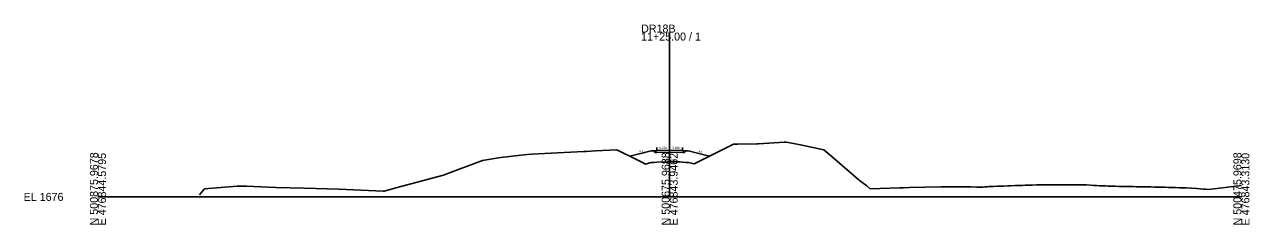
# Model space of a CAD drawing. Extents: x -26 to 403, y -10 to 2578.
# Drawn here: x -25.7 to 402.8, y 990.3 to 1060.4 of the extents above; entities that cross this region are included whole.
import ezdxf

# ---------------------------------------------------------------- set-up
doc = ezdxf.new("R2010")
doc.units = 0
for name, color, linetype in [('Exist Cross Section Cell', 7, 'Continuous'), ('Exist XS Center Line Elevation Label', 7, 'Continuous'), ('Exist XS Ground Line', 7, 'Continuous'), ('Prop XS Ditch Slope Text', 7, 'Continuous'), ('Prop XS Earthwork Shape', 7, 'Continuous'), ('Prop XS EOT Tick Mark', 7, 'Continuous'), ('Prop XS Finish Grade', 7, 'Continuous'), ('Prop XS Finish Grade Earthwork', 7, 'Continuous'), ('Prop XS Finish Grade Pavement', 7, 'Continuous'), ('Prop XS Hydro Typical Ditch Data', 7, 'Continuous'), ('Prop XS Pvmt Edge Slope', 7, 'Continuous'), ('Prop XS SE Text', 7, 'Continuous'), ('Prop XS Shoulder Borrow Shape', 7, 'Continuous'), ('Prop XS Subgrade Earthwork', 7, 'Continuous')]:
    doc.layers.add(name, color=color, linetype=linetype)

msp = doc.modelspace()

# ---------------------------------------------------------------- linework, layer by layer
at = {"layer": 'Exist Cross Section Cell'}
for p, q in [((200, 1000), (200, 1057.57)), ((0, 1000), (200, 1000)), ((200, 1000), (400, 1000))]:
    msp.add_line(p, q, dxfattribs=at)
at = {"layer": 'Exist XS Ground Line'}
msp.add_lwpolyline([(35.58, 1000.75), (37.28, 1002.81), (48.69, 1003.73), (52.02, 1003.71), (62.23, 1003.32), (72.12, 1003.1), (80.24, 1002.83), (84.26, 1002.72), (99.79, 1001.95), (100.15, 1002.02), (104.65, 1003.26), (120.85, 1007.62), (122.04, 1008.03), (134.49, 1012.78), (140.78, 1013.78), (150.17, 1014.86), (151.66, 1015.01), (160.86, 1015.41), (169.99, 1015.91), (170.86, 1015.94), (174.1, 1016.14), (181.48, 1016.52), (188.86, 1012.86), (190.02, 1012.28), (191.56, 1011.51), (193.11, 1011.9), (193.56, 1012.01), (194.3, 1012.08), (195.56, 1012.18), (199.05, 1012.26), (200.06, 1012.28), (203.54, 1012.22), (204.56, 1012.2), (205.82, 1012.1), (206.56, 1012.04), (208.1, 1011.66), (208.56, 1011.55), (210.7, 1012.61), (222.38, 1018.49), (223.38, 1018.49), (223.84, 1018.5), (230.53, 1018.54), (231.07, 1018.54), (240.09, 1019.12), (240.87, 1019.19), (245.74, 1018.23), (253.91, 1016.54), (256.9, 1014.02), (266.39, 1005.76), (268.96, 1003.88), (270.13, 1002.87), (280.36, 1003.17), (281.84, 1003.22), (283.73, 1003.29), (294.97, 1003.55), (305.36, 1003.47), (307.36, 1003.36), (309.54, 1003.38), (310.27, 1003.5), (310.68, 1003.53), (311.12, 1003.55), (311.77, 1003.58), (313.32, 1003.67), (314.7, 1003.73), (315.01, 1003.74), (315.81, 1003.76), (316.81, 1003.8), (318.31, 1003.85), (319.31, 1003.88), (320.8, 1003.94), (321.82, 1003.97), (323.31, 1004.03), (324.33, 1004.07), (325.81, 1004.11), (326.85, 1004.15), (328.29, 1004.2), (329.35, 1004.21), (330.79, 1004.26), (331.86, 1004.26), (333.3, 1004.27), (334.39, 1004.26), (335.82, 1004.26), (336.91, 1004.25), (338.33, 1004.25), (339.44, 1004.24), (340.83, 1004.24), (342.22, 1004.24), (343.27, 1004.23), (343.97, 1004.23), (345.28, 1004.18), (345.8, 1004.18), (347.2, 1004.1), (348.28, 1004.02), (348.97, 1003.97), (349.37, 1003.94), (350.42, 1003.87), (351.21, 1003.85), (352.45, 1003.82), (353.34, 1003.81), (354.47, 1003.77), (355.83, 1003.73), (357.15, 1003.69), (358.28, 1003.66), (359.66, 1003.62), (360.79, 1003.61), (362.17, 1003.59), (363.35, 1003.56), (364.46, 1003.54), (365.86, 1003.53), (366.96, 1003.52), (367.4, 1003.51), (368.32, 1003.49), (369.63, 1003.46), (370.81, 1003.44), (372.11, 1003.41), (373.3, 1003.38), (374.49, 1003.34), (375.79, 1003.29), (377, 1003.25), (378.29, 1003.21), (379.17, 1003.19), (379.47, 1003.18), (380.71, 1003.14), (384.43, 1002.88), (386.77, 1002.72), (387.39, 1002.68), (388.47, 1002.6), (390.43, 1002.81), (400, 1003.96)], dxfattribs=at)
at = {"layer": 'Prop XS Earthwork Shape'}
msp.add_lwpolyline([(193.5, 1016.09), (186.08, 1014.24), (188.86, 1012.86), (190.02, 1012.28), (191.56, 1011.51), (193.11, 1011.9), (193.56, 1012.01), (194.3, 1012.08), (195.56, 1012.18), (199.05, 1012.26), (200.06, 1012.28), (203.54, 1012.22), (204.56, 1012.2), (205.82, 1012.1), (206.56, 1012.04), (208.1, 1011.66), (208.56, 1011.55), (210.7, 1012.61), (213.93, 1014.24), (206.5, 1016.09), (205.76, 1016.15), (205.18, 1015.57), (204.5, 1015.59), (200, 1015.68), (195.5, 1015.59), (194.82, 1015.57), (194.24, 1016.15)], close=True, dxfattribs=at)
at = {"layer": 'Prop XS EOT Tick Mark'}
for p, q in [((195.5, 1016.25), (195.5, 1017.25)), ((204.5, 1016.25), (204.5, 1017.25))]:
    msp.add_line(p, q, dxfattribs=at)
at = {"layer": 'Prop XS Finish Grade'}
for p, q in [((195.5, 1016.25), (194.24, 1016.15)), ((204.5, 1016.25), (205.76, 1016.15))]:
    msp.add_line(p, q, dxfattribs=at)
at = {"layer": 'Prop XS Finish Grade Earthwork'}
for p, q in [((193.5, 1016.09), (186.08, 1014.24)), ((194.24, 1016.15), (193.5, 1016.09)), ((205.76, 1016.15), (206.5, 1016.09)), ((206.5, 1016.09), (213.93, 1014.24))]:
    msp.add_line(p, q, dxfattribs=at)
at = {"layer": 'Prop XS Finish Grade Pavement'}
for p, q in [((195.5, 1016.25), (200, 1016.34)), ((200, 1016.34), (204.5, 1016.25))]:
    msp.add_line(p, q, dxfattribs=at)
at = {"layer": 'Prop XS Hydro Typical Ditch Data'}
msp.add_line((193.5, 1016.09), (189.5, 1015.09), dxfattribs=at)
at = {"layer": 'Prop XS Pvmt Edge Slope'}
for p, q in [((195.5, 1016.25), (194.82, 1015.57)), ((204.5, 1016.25), (205.18, 1015.57))]:
    msp.add_line(p, q, dxfattribs=at)
at = {"layer": 'Prop XS Shoulder Borrow Shape'}
for points in [[(195.5, 1016.25), (194.82, 1015.57), (194.24, 1016.15)], [(205.18, 1015.57), (205.76, 1016.15), (204.5, 1016.25)]]:
    msp.add_lwpolyline(points, close=True, dxfattribs=at)
at = {"layer": 'Prop XS Subgrade Earthwork'}
for p, q in [((194.82, 1015.57), (194.24, 1016.15)), ((200, 1015.68), (195.5, 1015.59)), ((204.5, 1015.59), (200, 1015.68)), ((205.18, 1015.57), (205.76, 1016.15)), ((195.5, 1015.59), (194.82, 1015.57)), ((204.5, 1015.59), (205.18, 1015.57))]:
    msp.add_line(p, q, dxfattribs=at)

# ---------------------------------------------------------------- texts
at = {"layer": 'Exist Cross Section Cell'}
for s, p in [('DR18B', (190, 1057.57)), ('11+25.00 / 1', (190, 1054.77)), ('EL 1676', (-26, 998.6))]:
    msp.add_text(s, height=2.8, dxfattribs=at).set_placement(p)
for s, p in [('N 500875.9678', (0, 990)), ('E 476844.5795', (2.8, 990)), ('N 500675.9688', (200, 990)), ('E 476843.9462', (202.8, 990)), ('N 500475.9698', (400, 990)), ('E 476843.3130', (402.8, 990))]:
    msp.add_text(s, height=2.8, rotation=90, dxfattribs=at).set_placement(p)
at = {"layer": 'Exist XS Center Line Elevation Label'}
msp.add_text('1688.28', height=0.75, dxfattribs=at).set_placement((197.96, 1012.54))
at = {"layer": 'Prop XS Ditch Slope Text'}
for rotation, p in [(14.0362, (189.4, 1015.58)), (345.9638, (210.02, 1015.65))]:
    msp.add_text('4:1', height=0.75, rotation=rotation, dxfattribs=at).set_placement(p)
at = {"layer": 'Prop XS SE Text'}
for rotation, p in [(1.1458, (196.44, 1016.77)), (358.8542, (200.94, 1016.83))]:
    msp.add_text('0.020', height=0.75, rotation=rotation, dxfattribs=at).set_placement(p)

doc.saveas('drawing.dxf')
